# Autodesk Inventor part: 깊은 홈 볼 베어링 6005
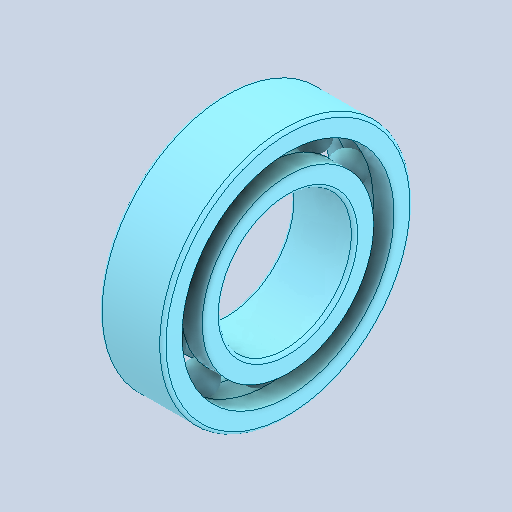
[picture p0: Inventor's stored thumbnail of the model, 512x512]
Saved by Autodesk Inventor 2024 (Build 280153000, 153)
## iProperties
Created: 2025-11
Part Number: 깊은 홈 볼 베어링 6005
Material: 강철, 연강
Description: 깊은 그루브 볼 베어링
Document SubType Name: Modeling
Designer: Edu07
Density: 7.85 g/cm^3
Appearance: 기본값
Author: jhkim
Sending System: Autodesk Inventor 2026
Preprocessor: ST-DEVELOPER v20.1
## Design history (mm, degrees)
node "깊은 홈 볼 베어링 60051"
node "솔리드1"
node "솔리드2"
node "솔리드3"
node "솔리드4"
node "솔리드5"
node "솔리드6"
node "솔리드7"
node "솔리드8"
node "솔리드9"
node "솔리드10"
node "솔리드11"
node "솔리드12"
body "Solid1"
node "Solid1:1"
node "Solid1:2"
node "Solid1:3"
node "Solid1:4"
node "Solid1:5"
node "Solid1:6"
node "Solid1:7"
node "Solid1:8"
node "Solid1:9"
node "Solid1:10"
node "Solid1:11"
